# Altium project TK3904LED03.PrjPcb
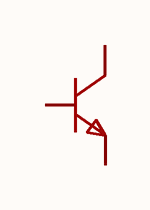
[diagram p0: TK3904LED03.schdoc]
1 sheet, 1 parts. Net scope: global (net labels, ports and power ports of the same name join across sheets).

## Sheet TK3904LED03.schdoc
size 127 x 101 mm

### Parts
Q?  tk3904led03  [DFN1006-3_L1.0-W0.6-P0.35-BR_BC846BM]  (value not drawn)

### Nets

Not connected (* = marked no-connect by the designer): Q? 1(B) 2(E) 3(C)

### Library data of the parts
Q? = tk3904led03: 晶体管类型:NPN;集电极电流(Ic):200mA;集射极击穿电压(Vceo):40V;耗散功率(Pd):100mW;直流电流增益(hFE):100;; Manufacturer: CJ(江苏长电/长晶); AddInBom: yes; ModelId: 7b69e286508f4c9e923f3d45e7d021d3; ModelName: DFN1006-3_L1.0-W0.6-H0.5-P0.35-BR_ BC846BM; ModelTransform: 40.1574,24.4094,0,0,0,0,0,0,0; type: NPN; Current - Collector(Ic): 200mA; Collector - Emitter Voltage VCEO: 40V; Pd - Power Dissipation: 100mW; DC Current Gain: 100; Transition frequency(fT): 300MHz; Current - Collector Cutoff: 100nA; Vce Saturation(VCE(sat)): 300mV; Emitter-Base Voltage(Vebo): 6V; Number: 1个NPN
